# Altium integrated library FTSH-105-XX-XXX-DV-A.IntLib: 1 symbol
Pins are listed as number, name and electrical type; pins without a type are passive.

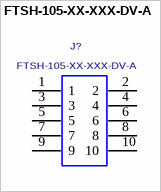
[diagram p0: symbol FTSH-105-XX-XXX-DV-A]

## FTSH-105-XX-XXX-DV-A
designator J?
0.050 INCH DOUBLE VERTICAL SMT TERMINAL STIP.; MANUFACTURER: SAMTEC
footprint FTSH-105-XX-XXX-DV-A
pins: 1, 2, 3, 4, 5, 6, 7, 8, 9, 10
